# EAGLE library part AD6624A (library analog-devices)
Four-Channel, 100 MSPS Digital Receive Signal Processor (RSP) Auto generated by make-symbol-device-package-bsdl.ulp Rev. 11 Source: 90033586AD6624A.bsdl.txt http://www.analog.com/UploadedFiles/Data_Sheets/171976900AD6624A_0.pdf
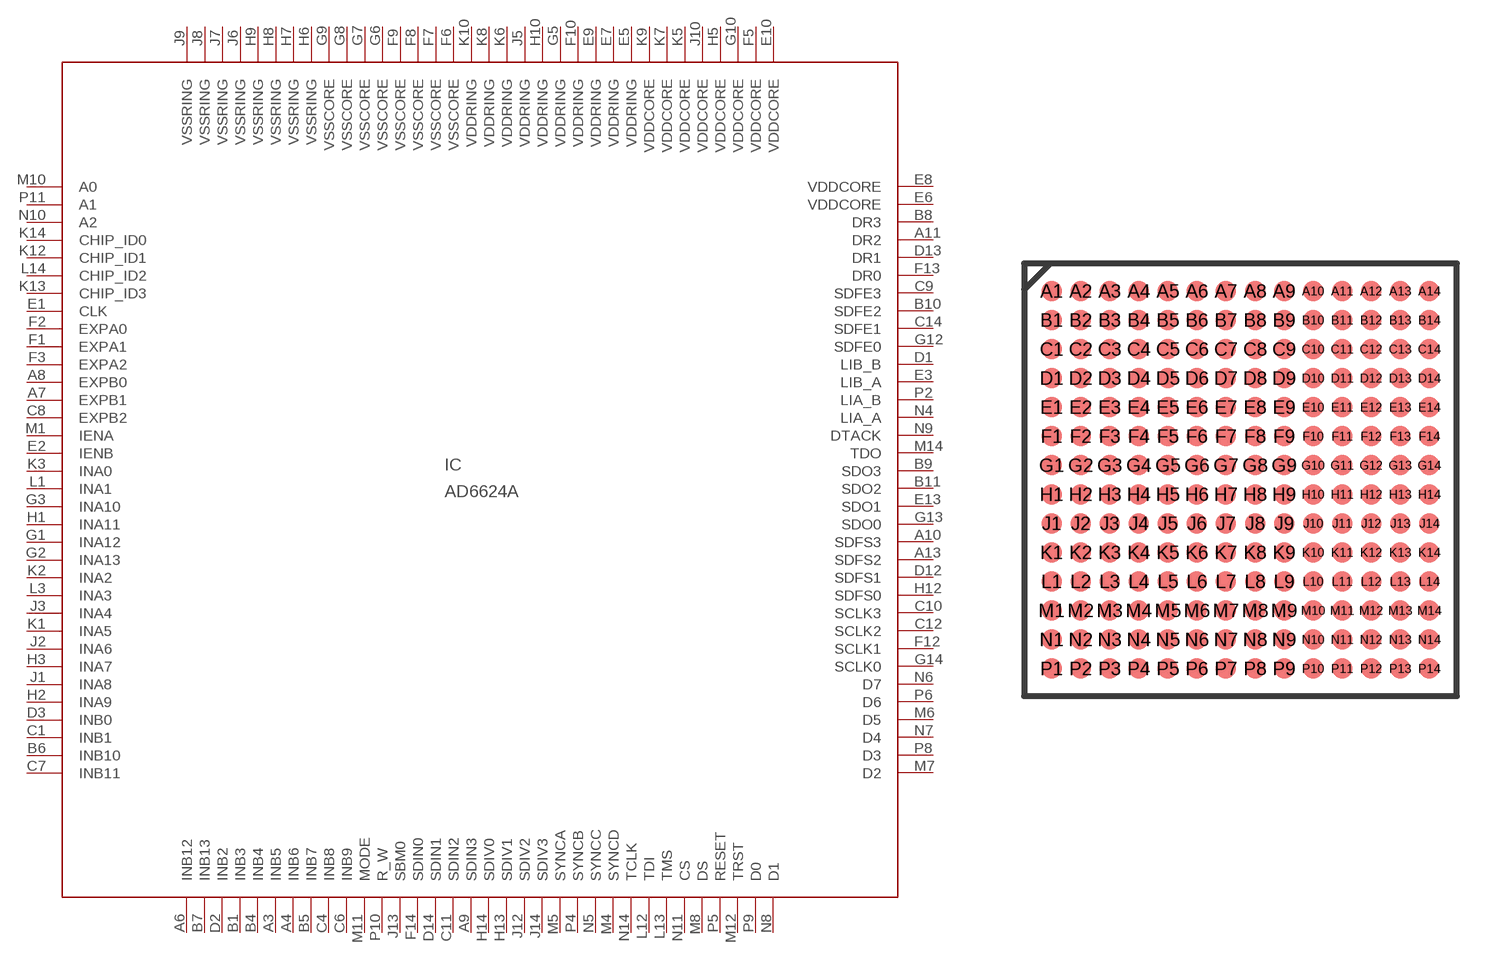
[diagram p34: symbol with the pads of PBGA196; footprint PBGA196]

Designator prefix IC

## AD6624A (MF: ALTERA CORPORATION; MPN: AD6624AABC; OC_FARNELL: unknown; OC_NEWARK: 94C0338)  [PBGA196]
A3  INB5  in
A4  INB6  in
A6  INB12  in
A7  EXPB1  in
A8  EXPB0  in
A9  SDIN3  in
A10  SDFS3
A11  DR2  hiz
A13  SDFS2
B1  INB3  in
B4  INB4  in
B5  INB7  in
B6  INB10  in
B7  INB13  in
B8  DR3  hiz
B9  SDO3  out
B10  SDFE2  hiz
B11  SDO2  out
C1  INB1  in
C4  INB8  in
C6  INB9  in
C7  INB11  in
C8  EXPB2  in
C9  SDFE3  hiz
C10  SCLK3
C11  SDIN2  in
C12  SCLK2
C14  SDFE1  hiz
D1  LIB_B  hiz
D2  INB2  in
D3  INB0  in
D12  SDFS1
D13  DR1  hiz
D14  SDIN1  in
E1  CLK  in
E2  IENB  in
E3  LIB_A  hiz
E5  VDDRING  pwr
E6  VDDCORE  pwr
E7  VDDRING  pwr
E8  VDDCORE  pwr
E9  VDDRING  pwr
E10  VDDCORE  pwr
E13  SDO1  out
F1  EXPA1  in
F2  EXPA0  in
F3  EXPA2  in
F5  VDDCORE  pwr
F6  VSSCORE  pwr
F7  VSSCORE  pwr
F8  VSSCORE  pwr
F9  VSSCORE  pwr
F10  VDDRING  pwr
F12  SCLK1
F13  DR0  hiz
F14  SDIN0  in
G1  INA12  in
G2  INA13  in
G3  INA10  in
G5  VDDRING  pwr
G6  VSSCORE  pwr
G7  VSSCORE  pwr
G8  VSSCORE  pwr
G9  VSSCORE  pwr
G10  VDDCORE  pwr
G12  SDFE0  hiz
G13  SDO0  out
G14  SCLK0
H1  INA11  in
H2  INA9  in
H3  INA7  in
H5  VDDCORE  pwr
H6  VSSRING  pwr
H7  VSSRING  pwr
H8  VSSRING  pwr
H9  VSSRING  pwr
H10  VDDRING  pwr
H12  SDFS0
H13  SDIV1  in
H14  SDIV0  in
J1  INA8  in
J2  INA6  in
J3  INA4  in
J5  VDDRING  pwr
J6  VSSRING  pwr
J7  VSSRING  pwr
J8  VSSRING  pwr
J9  VSSRING  pwr
J10  VDDCORE  pwr
J12  SDIV2  in
J13  SBM0  in
J14  SDIV3  in
K1  INA5  in
K2  INA2  in
K3  INA0  in
K5  VDDCORE  pwr
K6  VDDRING  pwr
K7  VDDCORE  pwr
K8  VDDRING  pwr
K9  VDDCORE  pwr
K10  VDDRING  pwr
K12  CHIP_ID1  in
K13  CHIP_ID3  in
K14  CHIP_ID0  in
L1  INA1  in
L3  INA3  in
L12  TDI  in
L13  TMS  in
L14  CHIP_ID2  in
M1  IENA  in
M4  SYNCD  in
M5  SYNCA  in
M6  D5
M7  D2
M8  DS  in
M10  A0  in
M11  MODE  in
M12  TRST  in
M14  TDO  out
N4  LIA_A  hiz
N5  SYNCC  in
N6  D7
N7  D4
N8  D1
N9  DTACK  out
N10  A2  in
N11  CS  in
N14  TCLK  in
P2  LIA_B  hiz
P4  SYNCB  in
P5  RESET  in
P6  D6
P8  D3
P9  D0
P10  R_W  in
P11  A1  in

## Footprint PBGA196 (pad centres in mm)
196-Lead PBGA (BC-196) Auto generated by make-symbol-device-package-bsdl.ulp Rev. 11 Source: 90033586AD6624A.bsdl.txt http://www.analog.com/UploadedFiles/Data_Sheets/171976900AD6624A_0.pdf
smd 0.7 x 0.7: A1 -6.5,6.5; A2 -5.5,6.5; A3 -4.5,6.5; A4 -3.5,6.5; A5 -2.5,6.5; A6 -1.5,6.5; A7 -0.5,6.5; A8 0.5,6.5; A9 1.5,6.5; A10 2.5,6.5; A11 3.5,6.5; A12 4.5,6.5; A13 5.5,6.5; A14 6.5,6.5; B1 -6.5,5.5; B2 -5.5,5.5; B3 -4.5,5.5; B4 -3.5,5.5; B5 -2.5,5.5; B6 -1.5,5.5; B7 -0.5,5.5; B8 0.5,5.5; B9 1.5,5.5; B10 2.5,5.5; B11 3.5,5.5; B12 4.5,5.5; B13 5.5,5.5; B14 6.5,5.5; C1 -6.5,4.5; C2 -5.5,4.5; C3 -4.5,4.5; C4 -3.5,4.5; C5 -2.5,4.5; C6 -1.5,4.5; C7 -0.5,4.5; C8 0.5,4.5; C9 1.5,4.5; C10 2.5,4.5; C11 3.5,4.5; C12 4.5,4.5; C13 5.5,4.5; C14 6.5,4.5; D1 -6.5,3.5; D2 -5.5,3.5; D3 -4.5,3.5; D4 -3.5,3.5; D5 -2.5,3.5; D6 -1.5,3.5; D7 -0.5,3.5; D8 0.5,3.5; D9 1.5,3.5; D10 2.5,3.5; D11 3.5,3.5; D12 4.5,3.5; D13 5.5,3.5; D14 6.5,3.5; E1 -6.5,2.5; E2 -5.5,2.5; E3 -4.5,2.5; E4 -3.5,2.5; E5 -2.5,2.5; E6 -1.5,2.5; E7 -0.5,2.5; E8 0.5,2.5; E9 1.5,2.5; E10 2.5,2.5; E11 3.5,2.5; E12 4.5,2.5; E13 5.5,2.5; E14 6.5,2.5; F1 -6.5,1.5; F2 -5.5,1.5; F3 -4.5,1.5; F4 -3.5,1.5; F5 -2.5,1.5; F6 -1.5,1.5; F7 -0.5,1.5; F8 0.5,1.5; F9 1.5,1.5; F10 2.5,1.5; F11 3.5,1.5; F12 4.5,1.5; F13 5.5,1.5; F14 6.5,1.5; G1 -6.5,0.5; G2 -5.5,0.5; G3 -4.5,0.5; G4 -3.5,0.5; G5 -2.5,0.5; G6 -1.5,0.5; G7 -0.5,0.5; G8 0.5,0.5; G9 1.5,0.5; G10 2.5,0.5; G11 3.5,0.5; G12 4.5,0.5; G13 5.5,0.5; G14 6.5,0.5; H1 -6.5,-0.5; H2 -5.5,-0.5; H3 -4.5,-0.5; H4 -3.5,-0.5; H5 -2.5,-0.5; H6 -1.5,-0.5; H7 -0.5,-0.5; H8 0.5,-0.5; H9 1.5,-0.5; H10 2.5,-0.5; H11 3.5,-0.5; H12 4.5,-0.5; H13 5.5,-0.5; H14 6.5,-0.5; J1 -6.5,-1.5; J2 -5.5,-1.5; J3 -4.5,-1.5; J4 -3.5,-1.5; J5 -2.5,-1.5; J6 -1.5,-1.5; J7 -0.5,-1.5; J8 0.5,-1.5; J9 1.5,-1.5; J10 2.5,-1.5; J11 3.5,-1.5; J12 4.5,-1.5; J13 5.5,-1.5; J14 6.5,-1.5; K1 -6.5,-2.5; K2 -5.5,-2.5; K3 -4.5,-2.5; K4 -3.5,-2.5; K5 -2.5,-2.5; K6 -1.5,-2.5; K7 -0.5,-2.5; K8 0.5,-2.5; K9 1.5,-2.5; K10 2.5,-2.5; K11 3.5,-2.5; K12 4.5,-2.5; K13 5.5,-2.5; K14 6.5,-2.5; L1 -6.5,-3.5; L2 -5.5,-3.5; L3 -4.5,-3.5; L4 -3.5,-3.5; L5 -2.5,-3.5; L6 -1.5,-3.5; L7 -0.5,-3.5; L8 0.5,-3.5; L9 1.5,-3.5; L10 2.5,-3.5; L11 3.5,-3.5; L12 4.5,-3.5; L13 5.5,-3.5; L14 6.5,-3.5; M1 -6.5,-4.5; M2 -5.5,-4.5; M3 -4.5,-4.5; M4 -3.5,-4.5; M5 -2.5,-4.5; M6 -1.5,-4.5; M7 -0.5,-4.5; M8 0.5,-4.5; M9 1.5,-4.5; M10 2.5,-4.5; M11 3.5,-4.5; M12 4.5,-4.5; M13 5.5,-4.5; M14 6.5,-4.5; N1 -6.5,-5.5; N2 -5.5,-5.5; N3 -4.5,-5.5; N4 -3.5,-5.5; N5 -2.5,-5.5; N6 -1.5,-5.5; N7 -0.5,-5.5; N8 0.5,-5.5; N9 1.5,-5.5; N10 2.5,-5.5; N11 3.5,-5.5; N12 4.5,-5.5; N13 5.5,-5.5; N14 6.5,-5.5; P1 -6.5,-6.5; P2 -5.5,-6.5; P3 -4.5,-6.5; P4 -3.5,-6.5; P5 -2.5,-6.5; P6 -1.5,-6.5; P7 -0.5,-6.5; P8 0.5,-6.5; P9 1.5,-6.5; P10 2.5,-6.5; P11 3.5,-6.5; P12 4.5,-6.5; P13 5.5,-6.5; P14 6.5,-6.5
